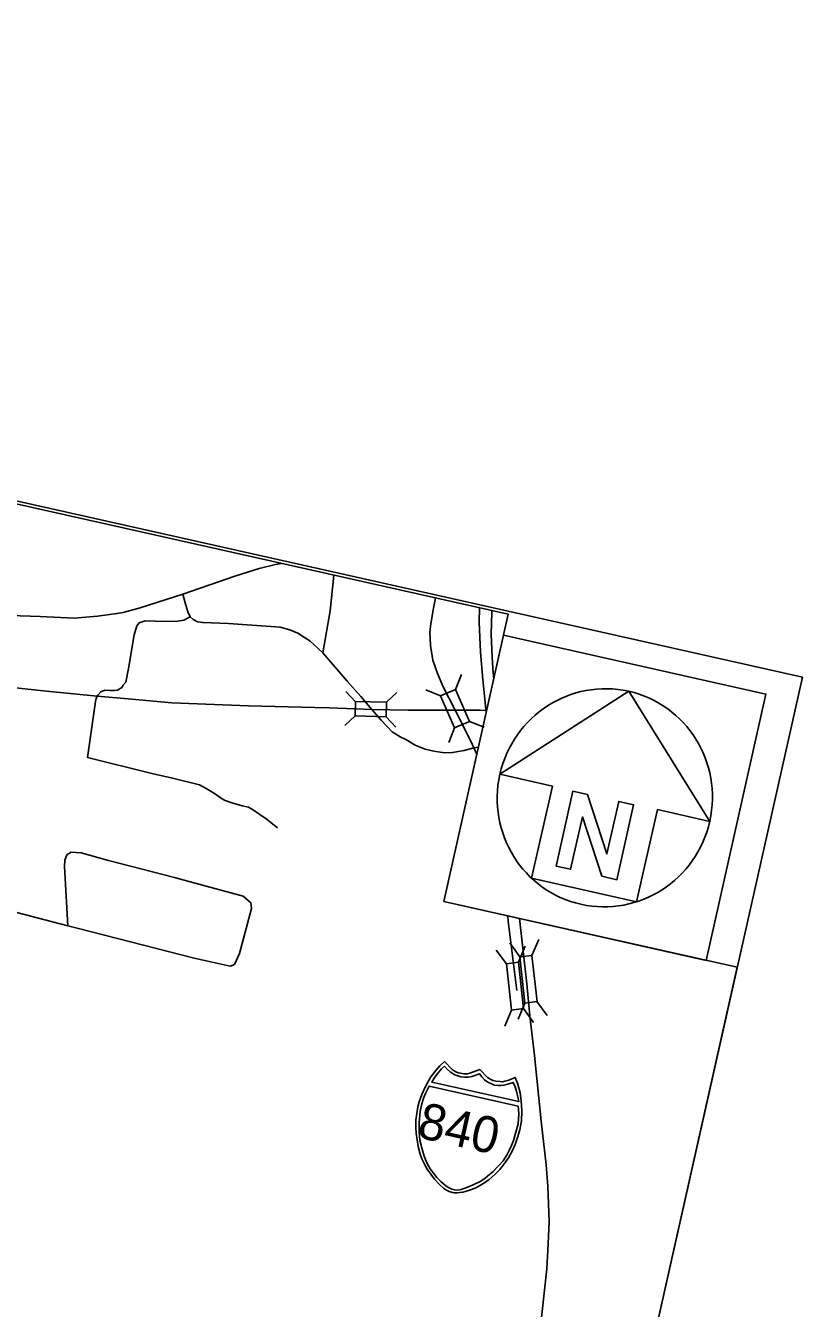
# Model space of a CAD drawing. Extents: x 1784499 to 1786147, y 841097 to 842538.
# Drawn here: x 1784969.2 to 1785099.6, y 842322.5 to 842538 of the extents above; entities that cross this region are included whole.
import ezdxf

# ---------------------------------------------------------------- set-up
doc = ezdxf.new("R2010")
doc.units = 0
for name, color, linetype in [('Exist Railroad Mainline', 7, 'Continuous'), ('Exist Railroad Structure Bridge CELL', 7, 'Continuous'), ('Exist Road Primary Interstate Divided Center Attributed', 7, 'Continuous'), ('Exist Road Primary Interstate Shield CELL', 7, 'Continuous'), ('Exist Road Primary Interstate Shield Number Label', 7, 'Continuous'), ('Exist Road Primary Interstate Structure Non-Sys NCDOT CELL', 7, 'Continuous'), ('Exist Road Primary US Attributed', 7, 'Continuous'), ('Exist Road Secondary Type 51 Attributed', 7, 'Continuous'), ('Old_Level_10', 7, 'Continuous'), ('Old_Level_40', 7, 'Continuous'), ('Prop Road Primary Interstate Projected', 7, 'Continuous'), ('Scratch_Level_3', 7, 'Continuous')]:
    doc.layers.add(name, color=color, linetype=linetype)

msp = doc.modelspace()

# ---------------------------------------------------------------- linework, layer by layer
at = {"layer": 'Exist Railroad Mainline'}
msp.add_lwpolyline([(1785046.61, 842422.95), (1785045.54, 842422.99), (1785033.4, 842423), (1785027.34, 842423.11), (1785020.23, 842423.39), (1785017.75, 842423.42), (1785006.59, 842423.69), (1784993.72, 842424.19), (1784986.4, 842424.89), (1784981.19, 842425.34), (1784972.67, 842426.19), (1784966.49, 842426.86), (1784960.81, 842427.46)], dxfattribs=at)
at = {"layer": 'Exist Railroad Structure Bridge CELL'}
for p, q in [((1785024.57, 842424.4), (1785022.94, 842426.13)), ((1785031.52, 842425.95), (1785029.79, 842424.31)), ((1785024.51, 842422.02), (1785022.79, 842420.38)), ((1785031.37, 842420.15), (1785029.73, 842421.88))]:
    msp.add_line(p, q, dxfattribs=at)
msp.add_lwpolyline([(1785029.73, 842421.88), (1785024.51, 842422.01), (1785024.58, 842424.45), (1785029.79, 842424.31)], close=True, dxfattribs=at)
at = {"layer": 'Exist Road Primary Interstate Divided Center Attributed'}
for points in [[(1785053.38, 842377.03), (1785052.14, 842387.98)], [(1785055.3, 842314.59), (1785055.85, 842320.96), (1785056.74, 842329.12), (1785056.94, 842333.35), (1785057.11, 842337.08), (1785056.88, 842342.99), (1785056.6, 842346.6), (1785055.76, 842353.95), (1785054.64, 842364.97), (1785053.89, 842371.63), (1785053.38, 842377.03)]]:
    msp.add_lwpolyline(points, dxfattribs=at)
at = {"layer": 'Exist Road Primary Interstate Shield CELL'}
for points in [[(1785040.85, 842341.94), (1785041.18, 842341.9), (1785041.63, 842341.88), (1785042.08, 842341.93), (1785042.6, 842342.03), (1785043.4, 842342.26), (1785044.04, 842342.47), (1785044.79, 842342.76), (1785045.86, 842343.37), (1785046.95, 842344.1), (1785047.96, 842344.98), (1785048.8, 842345.82), (1785049.6, 842346.82), (1785050.29, 842347.76), (1785050.92, 842348.88), (1785051.42, 842349.99), (1785051.81, 842351.17), (1785052.19, 842352.49), (1785052.44, 842354.02), (1785052.52, 842355.62), (1785052.49, 842356.64), (1785052.37, 842357.87), (1785052.23, 842358.67), (1785051.82, 842360.13), (1785051.41, 842361.28), (1785050.34, 842360.84), (1785049.67, 842360.65), (1785049.26, 842360.57), (1785048.87, 842360.58), (1785048.16, 842360.65), (1785047.72, 842360.77), (1785047.34, 842360.95), (1785047.01, 842361.1), (1785046.77, 842361.3), (1785045.49, 842362.61), (1785043.77, 842361.98), (1785043.42, 842361.9), (1785043.08, 842361.91), (1785042.76, 842361.89), (1785042.24, 842361.98), (1785041.85, 842362.08), (1785041.46, 842362.24), (1785041.16, 842362.38), (1785040.84, 842362.63), (1785039.53, 842363.94), (1785038.73, 842363.21), (1785038.05, 842362.46), (1785037.26, 842361.36), (1785036.72, 842360.49), (1785036.32, 842359.76), (1785035.72, 842358.4), (1785035.29, 842357.2), (1785035.07, 842356.33), (1785034.74, 842354.11), (1785034.72, 842352.89), (1785034.75, 842351.9), (1785035.11, 842349.68), (1785035.46, 842348.4), (1785035.8, 842347.47), (1785036.32, 842346.39), (1785036.62, 842345.86), (1785037.84, 842344.19), (1785038.7, 842343.27), (1785039.41, 842342.65), (1785039.76, 842342.42), (1785040.32, 842342.12)], [(1785039.55, 842363.2), (1785039.05, 842362.71), (1785038.45, 842362.03), (1785037.93, 842361.31), (1785037.38, 842360.5), (1785051.99, 842357.22), (1785051.83, 842358.05), (1785051.63, 842358.9), (1785051.41, 842359.68), (1785051.09, 842360.46), (1785050.16, 842360.13), (1785049.5, 842359.98), (1785048.98, 842359.92), (1785048.55, 842359.92), (1785047.91, 842360.01), (1785047.63, 842360.09), (1785046.8, 842360.49), (1785046.26, 842360.86), (1785045.78, 842361.37), (1785045.42, 842361.9), (1785044.1, 842361.46), (1785043.54, 842361.35), (1785042.91, 842361.33), (1785042.25, 842361.39), (1785041.28, 842361.73), (1785040.56, 842362.17), (1785039.96, 842362.67)], [(1785051.92, 842356.48), (1785051.98, 842356.03), (1785051.99, 842355.06), (1785051.95, 842354.33), (1785051.88, 842353.49), (1785051.53, 842352.11), (1785051.14, 842350.68), (1785050.81, 842349.86), (1785050.46, 842349.12), (1785050.03, 842348.31), (1785049.38, 842347.25), (1785048.62, 842346.41), (1785047.71, 842345.48), (1785046.77, 842344.7), (1785046.36, 842344.38), (1785045.62, 842343.88), (1785044.34, 842343.25), (1785043.4, 842342.83), (1785042.32, 842342.48), (1785041.79, 842342.37), (1785041.2, 842342.38), (1785040.74, 842342.52), (1785040.21, 842342.79), (1785039.79, 842343.02), (1785038.91, 842343.78), (1785038.22, 842344.5), (1785037.12, 842345.91), (1785036.59, 842346.93), (1785036.13, 842348.07), (1785035.76, 842349.23), (1785035.41, 842350.72), (1785035.26, 842352.17), (1785035.25, 842353.7), (1785035.43, 842355.54), (1785035.65, 842356.63), (1785035.95, 842357.66), (1785036.17, 842358.18), (1785036.46, 842358.83), (1785036.96, 842359.82)]]:
    msp.add_lwpolyline(points, close=True, dxfattribs=at)
at = {"layer": 'Exist Road Primary Interstate Structure Non-Sys NCDOT CELL'}
for p, q in [((1785042.37, 842428.98), (1785041.39, 842426.48)), ((1785036.38, 842426.38), (1785038.87, 842425.4)), ((1785043.71, 842421.1), (1785046.2, 842420.11)), ((1785041.2, 842420.01), (1785040.26, 842417.54)), ((1785055.35, 842384.48), (1785054.22, 842381.79)), ((1785048.23, 842382.69), (1785049.92, 842380.36)), ((1785050.49, 842383.87), (1785052.18, 842381.53)), ((1785053.09, 842383.31), (1785051.96, 842380.62)), ((1785053.03, 842373.76), (1785051.93, 842371.07)), ((1785055.06, 842374.02), (1785056.75, 842371.69)), ((1785050.77, 842372.59), (1785049.68, 842369.9)), ((1785052.8, 842372.84), (1785054.49, 842370.51))]:
    msp.add_line(p, q, dxfattribs=at)
for points in [[(1785041.39, 842426.48), (1785043.72, 842421.1), (1785041.2, 842420.01), (1785038.87, 842425.4)], [(1785051.96, 842380.62), (1785052.81, 842372.85), (1785050.77, 842372.59), (1785049.92, 842380.36)], [(1785054.22, 842381.79), (1785055.07, 842374.02), (1785053.03, 842373.76), (1785052.18, 842381.53)]]:
    msp.add_lwpolyline(points, close=True, dxfattribs=at)
at = {"layer": 'Exist Road Primary US Attributed'}
for points in [[(1784995.56, 842442.49), (1785004.29, 842445.51), (1785008.39, 842446.78), (1785011.15, 842447.45), (1785012.17, 842447.63)], [(1784960.56, 842439.07), (1784966.56, 842438.91), (1784971.59, 842438.72), (1784977.3, 842438.46), (1784981.26, 842438.78), (1784984.51, 842439.22), (1784985.56, 842439.4), (1784988.4, 842440.18), (1784995.56, 842442.49)]]:
    msp.add_lwpolyline(points, dxfattribs=at)
at = {"layer": 'Exist Road Secondary Type 51 Attributed'}
for points in [[(1785019.11, 842432.63), (1785020.32, 842439.65), (1785020.95, 842445.66)], [(1784995.56, 842442.49), (1784995.97, 842440.99), (1784996.42, 842439.51), (1784996.83, 842438.66)], [(1784996.83, 842438.66), (1784995.76, 842438.09), (1784994.66, 842437.94), (1784992.7, 842437.89), (1784989.28, 842437.98), (1784988.27, 842437.65), (1784987.84, 842437.15), (1784987.41, 842435.63), (1784986.44, 842429.98), (1784985.99, 842427.71), (1784985.54, 842427.2), (1784985.35, 842426.81), (1784984.62, 842426.35), (1784984.08, 842426.28), (1784983.4, 842426.29), (1784982.47, 842426.34), (1784981.79, 842426.08), (1784981.29, 842425.51), (1784981.09, 842425.13), (1784981.04, 842424.95)], [(1784996.83, 842438.66), (1784997.34, 842438.19), (1784998.03, 842437.84), (1784998.92, 842437.69), (1785003.27, 842437.52), (1785011.92, 842436.94), (1785013.54, 842436.49), (1785014.9, 842435.94), (1785016.02, 842435.2), (1785016.91, 842434.64), (1785019.11, 842432.63)], [(1785019.11, 842432.63), (1785023.18, 842427.88), (1785025.47, 842425.3), (1785027.34, 842423.11)], [(1784981.04, 842424.95), (1784980.89, 842424.46), (1784979.59, 842415.02), (1784990.4, 842412.32), (1784993.61, 842411.6), (1784998.38, 842410.43), (1784999.5, 842409.85), (1785000.88, 842408.99), (1785002.05, 842408.13), (1785002.69, 842407.83), (1785003.79, 842407.42), (1785005.53, 842406.92), (1785006.62, 842406.67), (1785007.3, 842406.31), (1785009.59, 842404.7), (1785011.49, 842403.24)], [(1785027.34, 842423.11), (1785028.89, 842421.32), (1785030.75, 842419.37), (1785032.09, 842418.51), (1785033.06, 842418.05), (1785034.63, 842417.12), (1785036.28, 842416.41), (1785037.75, 842416.08), (1785039.52, 842415.84), (1785040.88, 842415.85), (1785042.83, 842416.23), (1785044.46, 842416.63)], [(1785044.46, 842416.63), (1785045.22, 842416.76)], [(1784994.18, 842394.86), (1784983.12, 842397.73), (1784978.5, 842399.03), (1784976.8, 842399.1), (1784976.1, 842398.66), (1784975.77, 842397.76), (1784975.69, 842396.74), (1784975.78, 842395.73), (1784976.25, 842386.75)], [(1784991.18, 842382.92), (1784997.49, 842381.31), (1785003.54, 842379.95), (1785004.23, 842380.26), (1785005.1, 842382.08), (1785007.12, 842389.69), (1785007.02, 842390.64), (1785005.71, 842391.71), (1784996.8, 842394.17), (1784994.18, 842394.86)], [(1784955.43, 842392.21), (1784973.71, 842387.42), (1784976.25, 842386.75)], [(1784976.25, 842386.75), (1784977.84, 842386.34), (1784991.18, 842382.92)]]:
    msp.add_lwpolyline(points, dxfattribs=at)
at = {"layer": 'Old_Level_10'}
for p, q in [((1785070.48, 842426.15), (1785048.83, 842412.21)), ((1785084.09, 842404.3), (1785070.48, 842426.15)), ((1785048.83, 842412.21), (1785057.65, 842410.23)), ((1785057.65, 842410.23), (1785054.17, 842394.74)), ((1785071.8, 842390.78), (1785075.28, 842406.28)), ((1785075.28, 842406.28), (1785084.09, 842404.3)), ((1785054.17, 842394.74), (1785071.8, 842390.78))]:
    msp.add_line(p, q, dxfattribs=at)
for points in [[(1785039.41, 842390.83), (1785083.48, 842380.95), (1785093.52, 842425.68), (1785049.44, 842435.57)], [(1785061.1, 842409.37), (1785058.27, 842396.79), (1785060.72, 842396.25), (1785062.69, 842405.05), (1785065.97, 842395.07), (1785068.48, 842394.5), (1785071.3, 842407.08), (1785068.79, 842407.64), (1785066.81, 842398.84), (1785063.54, 842408.82)]]:
    msp.add_lwpolyline(points, close=True, dxfattribs=at)
msp.add_ellipse((1785066.46, 842408.26), major_axis=(4.01, 17.89), ratio=0.985213, dxfattribs=at)
at = {"layer": 'Old_Level_40'}
for p, q in [((1784611.59, 842537.98), (1785099.64, 842428.53)), ((1785099.64, 842428.53), (1784986.93, 841925.94))]:
    msp.add_line(p, q, dxfattribs=at)
at = {"layer": 'Prop Road Primary Interstate Projected'}
for points in [[(1785038.02, 842441.84), (1785037.67, 842440.12), (1785037.22, 842437.49), (1785037.06, 842436.13), (1785037.18, 842433.86), (1785037.58, 842431.36), (1785038.35, 842429.17), (1785039.28, 842426.91), (1785041.28, 842423.1), (1785043.95, 842417.78), (1785044.46, 842416.63)], [(1785045.42, 842440.18), (1785045.37, 842437.74), (1785045.59, 842432.71), (1785045.96, 842428.11), (1785046.46, 842423.15), (1785046.53, 842422.57)], [(1785047.79, 842428.22), (1785047.69, 842429.26), (1785047.54, 842431.91), (1785047.37, 842435.77), (1785047.49, 842439.4), (1785047.49, 842439.71)], [(1785044.46, 842416.63), (1785044.95, 842415.55)], [(1785050.15, 842388.42), (1785050.23, 842387.55), (1785051.67, 842375.87)]]:
    msp.add_lwpolyline(points, dxfattribs=at)
at = {"layer": 'Scratch_Level_3'}
msp.add_lwpolyline([(1785039.41, 842390.83), (1785050.23, 842439.1), (1784611.48, 842537.49), (1784510.23, 842085.98), (1784998.27, 841976.54), (1785088.7, 842379.78)], close=True, dxfattribs=at)

# ---------------------------------------------------------------- texts
at = {"layer": 'Exist Road Primary Interstate Shield Number Label'}
msp.add_text('840', height=6.075, rotation=347.3599, dxfattribs=at).set_placement((1785034.72, 842351.27))

doc.saveas('drawing.dxf')
